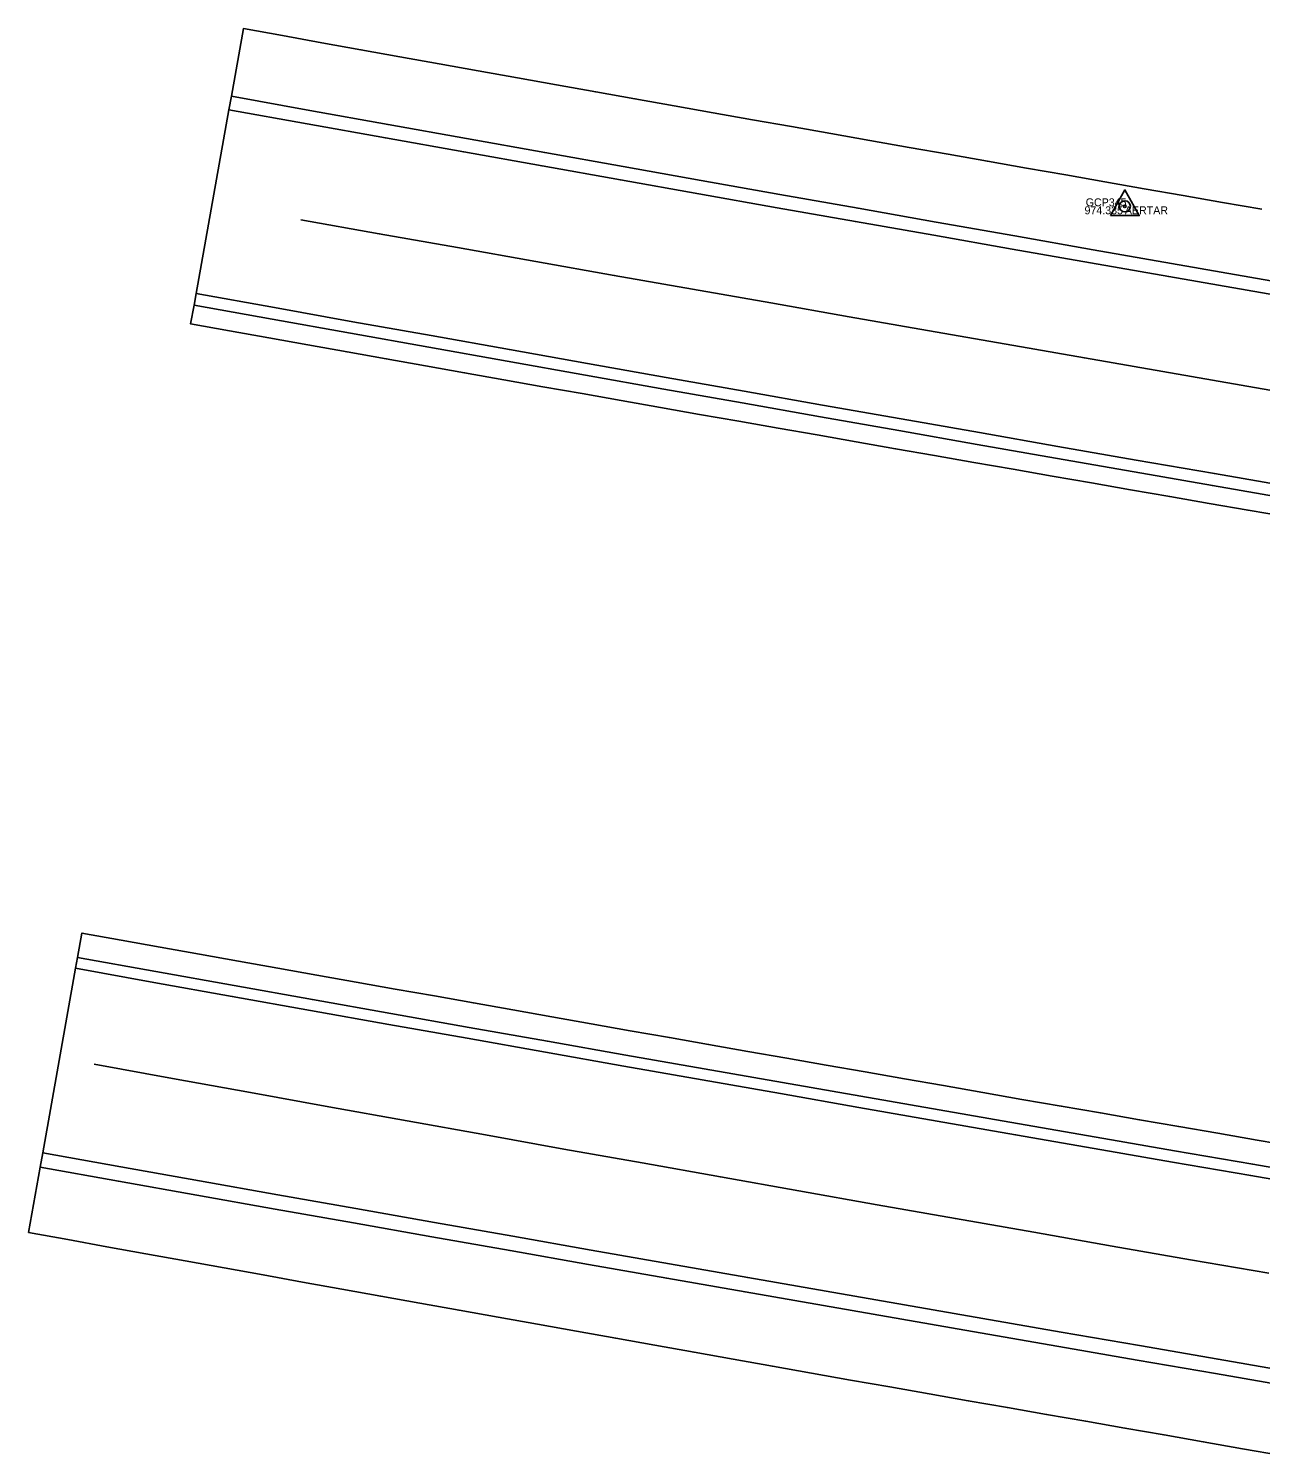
# Model space of a CAD drawing. Extents: x 2065431 to 2068157, y 709104 to 709719.
# Drawn here: x 2065626.9 to 2065781.8, y 709499.5 to 709678.8 of the extents above; entities that cross this region are included whole.
import ezdxf

# ---------------------------------------------------------------- set-up
doc = ezdxf.new("R2010")
doc.units = 0
for name, color, linetype in [('DT_X_Terrain_Boundary', 7, 'Continuous'), ('PM_X_Edge_Line', 7, 'Continuous'), ('PM_X_Lane_Line', 7, 'Continuous'), ('PV_X_EOP', 7, 'Continuous'), ('PV_X_Shoulder_Rumble_Strip', 7, 'Continuous'), ('SV_P_Aerial_Targets', 7, 'Continuous'), ('SV_X_Mon_Cells_Found', 7, 'Continuous'), ('SV_X_Text_Elevation', 7, 'Continuous'), ('SV_X_Text_Name', 7, 'Continuous')]:
    doc.layers.add(name, color=color, linetype=linetype)

msp = doc.modelspace()

# ---------------------------------------------------------------- linework, layer by layer
at = {"layer": 'DT_X_Terrain_Boundary'}
for points in [[(2065781.96, 709656.12), (2065777.03, 709656.98), (2065772.1, 709657.84), (2065767.18, 709658.7), (2065762.25, 709659.56), (2065757.33, 709660.43), (2065752.41, 709661.29), (2065747.48, 709662.16), (2065742.56, 709663.03), (2065737.63, 709663.89), (2065732.71, 709664.76), (2065727.79, 709665.64), (2065722.86, 709666.51), (2065717.94, 709667.38), (2065713.02, 709668.25), (2065708.09, 709669.13), (2065703.17, 709670.01), (2065698.25, 709670.88), (2065693.33, 709671.76), (2065688.4, 709672.64), (2065683.48, 709673.52), (2065678.56, 709674.41), (2065673.64, 709675.29), (2065668.72, 709676.18), (2065663.8, 709677.06), (2065658.88, 709677.95), (2065653.96, 709678.84), (2065652.46, 709670.32), (2065652.12, 709668.62), (2065648.01, 709645.52), (2065647.75, 709644.07), (2065647.31, 709641.71), (2065652.23, 709640.83), (2065657.15, 709639.95), (2065662.07, 709639.07), (2065667, 709638.19), (2065671.92, 709637.32), (2065676.84, 709636.44), (2065681.77, 709635.57), (2065686.69, 709634.7), (2065691.61, 709633.82), (2065696.54, 709632.95), (2065701.46, 709632.08), (2065706.38, 709631.21), (2065711.31, 709630.34), (2065716.23, 709629.48), (2065721.16, 709628.61), (2065726.08, 709627.75), (2065731, 709626.88), (2065735.93, 709626.02), (2065740.85, 709625.16), (2065745.78, 709624.29), (2065750.71, 709623.43), (2065755.63, 709622.57), (2065760.56, 709621.72), (2065765.48, 709620.86), (2065770.41, 709620), (2065775.34, 709619.15), (2065780.26, 709618.29), (2065785.19, 709617.44)], [(2065786.32, 709538.27), (2065781.39, 709539.12), (2065776.46, 709539.97), (2065771.53, 709540.82), (2065766.61, 709541.68), (2065761.68, 709542.53), (2065756.76, 709543.39), (2065751.83, 709544.24), (2065746.9, 709545.1), (2065741.98, 709545.96), (2065737.05, 709546.82), (2065732.13, 709547.68), (2065727.2, 709548.54), (2065722.28, 709549.41), (2065717.35, 709550.27), (2065712.43, 709551.14), (2065707.5, 709552), (2065702.58, 709552.87), (2065697.66, 709553.74), (2065692.73, 709554.61), (2065687.81, 709555.48), (2065682.88, 709556.35), (2065677.96, 709557.23), (2065673.04, 709558.1), (2065668.12, 709558.98), (2065663.19, 709559.85), (2065658.27, 709560.73), (2065653.35, 709561.61), (2065648.43, 709562.49), (2065643.5, 709563.37), (2065638.58, 709564.25), (2065633.66, 709565.14), (2065633.11, 709562.05), (2065632.87, 709560.71), (2065628.73, 709537.5), (2065628.41, 709535.7), (2065626.95, 709527.52)], [(2065626.95, 709527.52), (2065631.87, 709526.62), (2065636.79, 709525.72), (2065641.7, 709524.83), (2065646.62, 709523.94), (2065651.54, 709523.05), (2065656.46, 709522.16), (2065661.38, 709521.27), (2065666.31, 709520.38), (2065671.23, 709519.49), (2065676.15, 709518.61), (2065681.07, 709517.72), (2065685.99, 709516.84), (2065690.91, 709515.96), (2065695.83, 709515.08), (2065700.76, 709514.2), (2065705.68, 709513.33), (2065710.6, 709512.45), (2065715.52, 709511.58), (2065720.45, 709510.7), (2065725.37, 709509.83), (2065730.29, 709508.96), (2065735.22, 709508.09), (2065740.14, 709507.23), (2065745.07, 709506.36), (2065749.99, 709505.49), (2065754.92, 709504.63), (2065759.84, 709503.77), (2065764.77, 709502.91), (2065769.69, 709502.05), (2065774.62, 709501.19), (2065779.54, 709500.33), (2065784.47, 709499.48)]]:
    msp.add_lwpolyline(points, dxfattribs=at)
at = {"layer": 'PM_X_Edge_Line'}
for points in [[(2065652.12, 709668.62), (2065661.97, 709666.85), (2065671.81, 709665.08), (2065681.65, 709663.32), (2065691.5, 709661.56), (2065701.34, 709659.81), (2065711.19, 709658.06), (2065721.04, 709656.32), (2065730.88, 709654.58), (2065740.73, 709652.85), (2065750.58, 709651.11), (2065760.43, 709649.39), (2065770.28, 709647.66), (2065780.13, 709645.95), (2065789.98, 709644.23)], [(2065648.01, 709645.52), (2065657.85, 709643.76), (2065667.7, 709641.99), (2065677.54, 709640.24), (2065687.39, 709638.48), (2065697.23, 709636.73), (2065707.08, 709634.99), (2065716.92, 709633.25), (2065726.77, 709631.51), (2065736.62, 709629.78), (2065746.47, 709628.05), (2065756.32, 709626.32), (2065766.17, 709624.6), (2065776.02, 709622.89), (2065785.88, 709621.18)], [(2065632.87, 709560.71), (2065642.71, 709558.94), (2065652.56, 709557.18), (2065662.4, 709555.42), (2065672.25, 709553.66), (2065682.09, 709551.91), (2065691.94, 709550.16), (2065701.79, 709548.42), (2065711.63, 709546.69), (2065721.48, 709544.96), (2065731.33, 709543.23), (2065741.18, 709541.5), (2065751.03, 709539.79), (2065760.89, 709538.07), (2065770.74, 709536.36), (2065780.59, 709534.66), (2065790.45, 709532.96)], [(2065628.73, 709537.5), (2065638.57, 709535.75), (2065648.42, 709534), (2065658.27, 709532.25), (2065668.11, 709530.5), (2065677.96, 709528.76), (2065687.81, 709527.03), (2065697.66, 709525.3), (2065707.51, 709523.57), (2065717.36, 709521.84), (2065727.21, 709520.12), (2065737.06, 709518.4), (2065746.91, 709516.69), (2065756.76, 709514.98), (2065766.62, 709513.28), (2065776.47, 709511.57), (2065786.33, 709509.88)]]:
    msp.add_lwpolyline(points, dxfattribs=at)
at = {"layer": 'PM_X_Lane_Line'}
for points in [[(2065661.19, 709654.8), (2065671.04, 709653.05), (2065680.88, 709651.3), (2065690.73, 709649.55), (2065700.58, 709647.81), (2065710.42, 709646.07), (2065720.27, 709644.34), (2065730.12, 709642.61), (2065739.97, 709640.88), (2065749.82, 709639.16), (2065759.67, 709637.44), (2065769.53, 709635.73), (2065779.38, 709634.02), (2065789.23, 709632.31)], [(2065635.19, 709548.65), (2065645.03, 709546.86), (2065654.87, 709545.08), (2065664.71, 709543.3), (2065674.55, 709541.52), (2065684.39, 709539.76), (2065694.23, 709537.99), (2065704.08, 709536.24), (2065713.92, 709534.49), (2065723.77, 709532.74), (2065733.62, 709531), (2065743.47, 709529.26), (2065753.32, 709527.53), (2065763.16, 709525.8), (2065773.02, 709524.08), (2065782.87, 709522.37)]]:
    msp.add_lwpolyline(points, dxfattribs=at)
at = {"layer": 'PV_X_EOP'}
for points in [[(2065653.96, 709678.84), (2065658.88, 709677.95), (2065663.8, 709677.06), (2065668.72, 709676.18), (2065673.64, 709675.29), (2065678.56, 709674.41), (2065683.48, 709673.52), (2065688.4, 709672.64), (2065693.33, 709671.76), (2065698.25, 709670.88), (2065703.17, 709670.01), (2065708.09, 709669.13), (2065713.02, 709668.25), (2065717.94, 709667.38), (2065722.86, 709666.51), (2065727.79, 709665.64), (2065732.71, 709664.76), (2065737.63, 709663.89), (2065742.56, 709663.03), (2065747.48, 709662.16), (2065752.41, 709661.29), (2065757.33, 709660.43), (2065762.25, 709659.56), (2065767.18, 709658.7), (2065772.1, 709657.84), (2065777.03, 709656.98), (2065781.96, 709656.12)], [(2065647.31, 709641.71), (2065652.23, 709640.83), (2065657.15, 709639.95), (2065662.07, 709639.07), (2065667, 709638.19), (2065671.92, 709637.32), (2065676.84, 709636.44), (2065681.77, 709635.57), (2065686.69, 709634.7), (2065691.61, 709633.82), (2065696.54, 709632.95), (2065701.46, 709632.08), (2065706.38, 709631.21), (2065711.31, 709630.34), (2065716.23, 709629.48), (2065721.16, 709628.61), (2065726.08, 709627.75), (2065731, 709626.88), (2065735.93, 709626.02), (2065740.85, 709625.16), (2065745.78, 709624.29), (2065750.71, 709623.43), (2065755.63, 709622.57), (2065760.56, 709621.72), (2065765.48, 709620.86), (2065770.41, 709620), (2065775.34, 709619.15), (2065780.26, 709618.29), (2065785.19, 709617.44)], [(2065633.66, 709565.14), (2065638.58, 709564.25), (2065643.5, 709563.37), (2065648.43, 709562.49), (2065653.35, 709561.61), (2065658.27, 709560.73), (2065663.19, 709559.85), (2065668.12, 709558.98), (2065673.04, 709558.1), (2065677.96, 709557.23), (2065682.88, 709556.35), (2065687.81, 709555.48), (2065692.73, 709554.61), (2065697.66, 709553.74), (2065702.58, 709552.87), (2065707.5, 709552), (2065712.43, 709551.14), (2065717.35, 709550.27), (2065722.28, 709549.41), (2065727.2, 709548.54), (2065732.13, 709547.68), (2065737.05, 709546.82), (2065741.98, 709545.96), (2065746.9, 709545.1), (2065751.83, 709544.24), (2065756.76, 709543.39), (2065761.68, 709542.53), (2065766.61, 709541.68), (2065771.53, 709540.82), (2065776.46, 709539.97), (2065781.39, 709539.12), (2065786.32, 709538.27)], [(2065626.95, 709527.52), (2065631.87, 709526.62), (2065636.79, 709525.72), (2065641.7, 709524.83), (2065646.62, 709523.94), (2065651.54, 709523.05), (2065656.46, 709522.16), (2065661.38, 709521.27), (2065666.31, 709520.38), (2065671.23, 709519.49), (2065676.15, 709518.61), (2065681.07, 709517.72), (2065685.99, 709516.84), (2065690.91, 709515.96), (2065695.83, 709515.08), (2065700.76, 709514.2), (2065705.68, 709513.33), (2065710.6, 709512.45), (2065715.52, 709511.58), (2065720.45, 709510.7), (2065725.37, 709509.83), (2065730.29, 709508.96), (2065735.22, 709508.09), (2065740.14, 709507.23), (2065745.07, 709506.36), (2065749.99, 709505.49), (2065754.92, 709504.63), (2065759.84, 709503.77), (2065764.77, 709502.91), (2065769.69, 709502.05), (2065774.62, 709501.19), (2065779.54, 709500.33), (2065784.47, 709499.48)]]:
    msp.add_lwpolyline(points, dxfattribs=at)
at = {"layer": 'PV_X_Shoulder_Rumble_Strip'}
for points in [[(2065652.46, 709670.32), (2065662.3, 709668.54), (2065672.15, 709666.77), (2065681.99, 709665.01), (2065691.83, 709663.24), (2065701.68, 709661.49), (2065711.52, 709659.73), (2065721.37, 709657.99), (2065731.22, 709656.24), (2065741.06, 709654.5), (2065750.91, 709652.77), (2065760.76, 709651.04), (2065770.61, 709649.31), (2065780.46, 709647.59), (2065790.31, 709645.87)], [(2065647.75, 709644.07), (2065657.59, 709642.3), (2065667.44, 709640.54), (2065677.28, 709638.78), (2065687.12, 709637.02), (2065696.97, 709635.26), (2065706.82, 709633.51), (2065716.66, 709631.77), (2065726.51, 709630.03), (2065736.36, 709628.29), (2065746.21, 709626.56), (2065756.06, 709624.83), (2065765.91, 709623.11), (2065775.76, 709621.39), (2065785.61, 709619.68)], [(2065633.11, 709562.05), (2065642.95, 709560.29), (2065652.8, 709558.53), (2065662.64, 709556.78), (2065672.49, 709555.03), (2065682.34, 709553.28), (2065692.18, 709551.54), (2065702.03, 709549.81), (2065711.88, 709548.07), (2065721.73, 709546.35), (2065731.58, 709544.62), (2065741.43, 709542.9), (2065751.28, 709541.19), (2065761.14, 709539.48), (2065770.99, 709537.77), (2065780.84, 709536.07), (2065790.7, 709534.38)], [(2065628.41, 709535.7), (2065638.25, 709533.94), (2065648.1, 709532.19), (2065657.94, 709530.44), (2065667.79, 709528.7), (2065677.64, 709526.96), (2065687.49, 709525.22), (2065697.33, 709523.49), (2065707.18, 709521.76), (2065717.03, 709520.04), (2065726.89, 709518.32), (2065736.74, 709516.6), (2065746.59, 709514.89), (2065756.44, 709513.18), (2065766.3, 709511.47), (2065776.15, 709509.77), (2065786, 709508.07)]]:
    msp.add_lwpolyline(points, dxfattribs=at)
at = {"layer": 'SV_P_Aerial_Targets'}
msp.add_lwpolyline([(2065762.96, 709655.33), (2065766.56, 709655.33), (2065764.76, 709658.55)], close=True, dxfattribs=at)
for radius in [0.7, 0.16]:
    msp.add_circle((2065764.76, 709656.49), radius, dxfattribs=at)

# ---------------------------------------------------------------- texts
at = {"layer": 'SV_X_Mon_Cells_Found'}
msp.add_text('GCP345', height=1, dxfattribs=at).set_placement((2065759.84, 709656.49))
at = {"layer": 'SV_X_Text_Elevation'}
msp.add_text('AERTAR', height=1, dxfattribs=at).set_placement((2065764.76, 709655.49))
at = {"layer": 'SV_X_Text_Name'}
msp.add_text('974.335', height=1, dxfattribs=at).set_placement((2065759.69, 709655.49))

doc.saveas('drawing.dxf')
